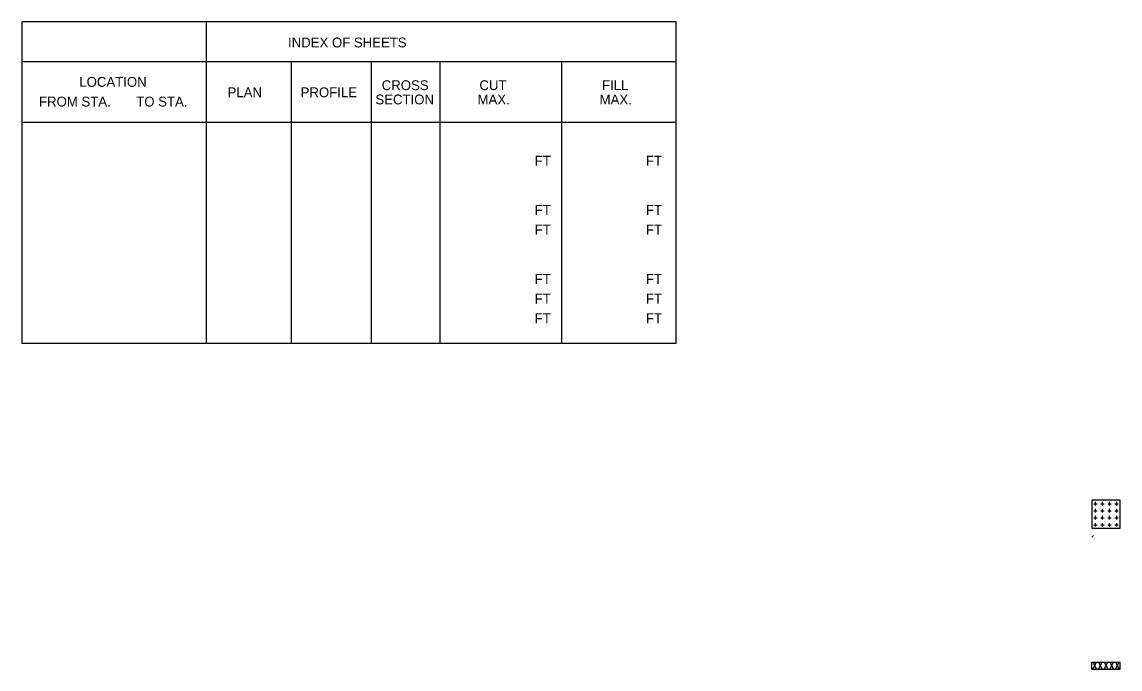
# Model space of a CAD drawing. Extents: x -59 to 43, y 0 to 22.
# Drawn here: x -25.52 to -9.92, y 2.12 to 11.31 of the extents above; entities that cross this region are included whole.
import ezdxf

# ---------------------------------------------------------------- set-up
doc = ezdxf.new("R2010")
doc.units = 0
for name, color, linetype in [('Default', 7, 'Continuous'), ('GT_Project_Soil_Layers', 7, 'Continuous'), ('SH_Data', 7, 'Continuous'), ('SH_Text', 7, 'Continuous')]:
    doc.layers.add(name, color=color, linetype=linetype)

msp = doc.modelspace()

# ---------------------------------------------------------------- linework, layer by layer
at = {"layer": 'Default'}
msp.add_line((-10.319, 3.99), (-10.297, 4.016), dxfattribs=at)
at = {"layer": 'GT_Project_Soil_Layers'}
for p, q in [((-10.306, 2.216), (-10.253, 2.116)), ((-10.306, 2.116), (-10.253, 2.216)), ((-10.226, 2.116), (-10.173, 2.216)), ((-10.226, 2.216), (-10.173, 2.116)), ((-10.146, 2.216), (-10.093, 2.116)), ((-10.146, 2.116), (-10.093, 2.216)), ((-10.066, 2.216), (-10.013, 2.116)), ((-10.066, 2.116), (-10.013, 2.216)), ((-9.986, 2.216), (-9.933, 2.116)), ((-9.986, 2.116), (-9.933, 2.216))]:
    msp.add_line(p, q, dxfattribs=at)
at = {"layer": 'SH_Data'}
for p, q in [((-25.524, 11.312), (-25.524, 6.747)), ((-22.905, 11.312), (-22.905, 6.747)), ((-25.524, 10.75), (-16.226, 10.75)), ((-21.696, 6.747), (-21.696, 10.75)), ((-20.558, 6.747), (-20.558, 10.75)), ((-19.58, 6.747), (-19.58, 10.75)), ((-17.853, 6.747), (-17.853, 10.75)), ((-25.524, 9.886), (-16.226, 9.886)), ((-25.524, 6.747), (-16.226, 6.747)), ((-10.319, 2.116), (-10.319, 2.216)), ((-10.319, 2.216), (-9.919, 2.216)), ((-9.919, 2.116), (-9.919, 2.216)), ((-10.319, 2.116), (-9.919, 2.116))]:
    msp.add_line(p, q, dxfattribs=at)
msp.add_lwpolyline([(-16.226, 6.747), (-16.226, 11.312), (-25.524, 11.312)], dxfattribs=at)
msp.add_lwpolyline([(-10.319, 4.116), (-9.919, 4.116), (-9.919, 4.516), (-10.319, 4.516)], close=True, dxfattribs=at)
at = {"layer": 'SH_Text'}
for p, q in [((-10.319, 4.516), (-10.319, 4.516)), ((-10.294, 4.466), (-10.244, 4.466)), ((-10.269, 4.441), (-10.269, 4.491)), ((-10.269, 4.341), (-10.269, 4.391)), ((-10.194, 4.466), (-10.144, 4.466)), ((-10.169, 4.441), (-10.169, 4.491)), ((-10.169, 4.341), (-10.169, 4.391)), ((-10.094, 4.466), (-10.044, 4.466)), ((-10.069, 4.441), (-10.069, 4.491)), ((-10.069, 4.341), (-10.069, 4.391)), ((-9.994, 4.466), (-9.969, 4.466)), ((-9.969, 4.491), (-9.969, 4.441)), ((-9.969, 4.466), (-9.944, 4.466)), ((-9.969, 4.391), (-9.969, 4.341)), ((-9.919, 4.516), (-9.919, 4.516)), ((-10.294, 4.366), (-10.244, 4.366)), ((-10.294, 4.266), (-10.244, 4.266)), ((-10.269, 4.241), (-10.269, 4.291)), ((-10.194, 4.366), (-10.144, 4.366)), ((-10.194, 4.266), (-10.144, 4.266)), ((-10.169, 4.241), (-10.169, 4.291)), ((-10.094, 4.366), (-10.044, 4.366)), ((-10.094, 4.266), (-10.044, 4.266)), ((-10.069, 4.241), (-10.069, 4.291)), ((-9.994, 4.366), (-9.969, 4.366)), ((-9.994, 4.266), (-9.969, 4.266)), ((-9.969, 4.366), (-9.944, 4.366)), ((-9.969, 4.291), (-9.969, 4.241)), ((-9.969, 4.266), (-9.944, 4.266)), ((-10.319, 4.116), (-10.319, 4.116)), ((-10.294, 4.166), (-10.244, 4.166)), ((-10.269, 4.141), (-10.269, 4.191)), ((-10.194, 4.166), (-10.144, 4.166)), ((-10.169, 4.141), (-10.169, 4.191)), ((-10.094, 4.166), (-10.044, 4.166)), ((-10.069, 4.141), (-10.069, 4.191)), ((-9.994, 4.166), (-9.969, 4.166)), ((-9.969, 4.191), (-9.969, 4.141)), ((-9.969, 4.166), (-9.944, 4.166)), ((-9.919, 4.116), (-9.919, 4.116))]:
    msp.add_line(p, q, dxfattribs=at)

# ---------------------------------------------------------------- texts
for s, p in [('INDEX OF SHEETS', (-21.743, 10.95)), ('LOCATION', (-24.709, 10.39)), ('CROSS', (-20.411, 10.343)), ('CUT', (-19.023, 10.343)), ('FILL', (-17.281, 10.343)), ('PLAN', (-22.602, 10.242)), ('PROFILE', (-21.564, 10.242)), ('FROM STA.', (-25.282, 10.11)), ('TO STA.', (-23.9, 10.11)), ('SECTION', (-20.501, 10.14)), ('MAX.', (-19.05, 10.14)), ('MAX.', (-17.315, 10.14)), ('FT', (-18.237, 9.27)), ('FT', (-16.657, 9.27)), ('FT', (-18.237, 8.57)), ('FT', (-16.657, 8.57)), ('FT', (-18.237, 8.29)), ('FT', (-16.657, 8.29)), ('FT', (-18.237, 7.59)), ('FT', (-16.657, 7.59)), ('FT', (-18.237, 7.31)), ('FT', (-16.657, 7.31)), ('FT', (-18.237, 7.03)), ('FT', (-16.657, 7.03))]:
    msp.add_text(s, height=0.14, dxfattribs=at).set_placement(p)

doc.saveas('drawing.dxf')
